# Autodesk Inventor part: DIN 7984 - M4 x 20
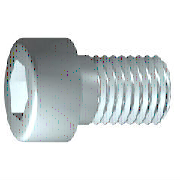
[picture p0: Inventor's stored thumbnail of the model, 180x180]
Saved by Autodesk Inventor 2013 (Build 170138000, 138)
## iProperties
Created: 2012-02
Part Number: DIN 7984 - M4 x 20
Material: Stahl, weich
Description: Zylinderkopfschraube
Document SubType Name: Modeling
Standard: DIN 7984
Designer: Ente
Standard Revision: 1985
Standards Organization: DIN
Language: de-DE
Size Designation: M4 x 20
Categories: <MemberInstance><Categories><Category DisplayName="Verbindungselemente" InternalName="e4da775c-781d-43d5-af7c-5136215cf5a6" Mnemonic="FSTN"><Category DisplayNam
Density: 1 g/cm^3
IsCustomPart: 0
Author: Ente
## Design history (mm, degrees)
sketch "Skizze1"
  geometry: L1 (0.333, 0)-(20, 0); L2 (20, 0)-(20, 2); L3 (20, 2)-(2.1, 2); L4 (2.1, 2)-(1.67, 2); L5 (1.67, 2)-(0, 2); L6 (0, 2)-(0, 3.5); L7 (0, 3.5)-(-2.8, 3.5); L8 (-2.8, 3.5)-(-2.8, 1.443); L9 (-2.8, 1.443)-(-0.5, 1.443); L10 (-0.5, 1.443)-(0.333, 0); L11 (-7.36, 0)-(24.56, 0) reference; L12 (0, -0.7)-(0, 4.2) reference; L13 (2.1, 2)-(0, 2)
  constraints: 22 end point, 6 parallel, 2 collinear, 2 perpendicular, 1 horizontal, 1 point on line
  dimensions: "d1" = 17.9 distance from line of L3.end L2 (= GEL); "d2" = 0.42952 distance of L4.end L3.end (computed from GAL); "d3" = 2.8 distance between parallel lines of L8 L6 (= KOH); "d4" = 2.3 distance of L8.end L9.end (= INTI); "d5" = 60 deg angle of L10 L1; "d6" = 4 diameter of L3 L1 (= GD); "d7" = 4 diameter of L5 L1 (= BDM); "d8" = 2.88675 diameter of L9 L1 (= 1.1547 x SW); "d9" = 7 diameter of L7 L1 (= KOD); "d26" = 20 distance between parallel lines of L12 L2 (= NLG)
revolve "Körper" sketch "Skizze1" stored, may be unused: angle "d10" = 90 deg
sketch "Skizze2"
  geometry: L1 (0, -4.9)-(0, 4.9) reference; L2 (-4.9, 0)-(4.9, 0) reference; L3 (1.443, 0)-(0.722, -1.25); L4 (0.722, -1.25)-(-0.722, -1.25); L5 (-0.722, -1.25)-(-1.443, 0); L6 (-1.443, 0)-(-0.722, 1.25); L7 (-0.722, 1.25)-(0.722, 1.25); L8 (0.722, 1.25)-(1.443, 0); 2 further points
  constraints: 12 end point, 1 coincident, 1 horizontal alignment, 1 point on line, 12 other
extrude "Loch" join sketch "Skizze2" stored distance "d11" = 10; taper "d12" = 0 deg
workplane "Work Plane1"
fillet "Fillet2" dims "d30" = 0.1 (= R)
body "Solid1"
fillet "Rundung1" dims "d17" = 0.4 (= RR)
feature "Gewinde" dims "d13" = 17.9 (= GEL), "d14" = 0
chamfer "Fase1" distance "d15" = 0.42941 (= -0.5 x SPD + 0.5 x GD); stored, may be unused: second distance "d16" = 0.42941 (= GUL), angle "d27" = 45 deg
other parameters: "GD" = 4 (= NND) [user parameter; used in 2 equation terms], "NLG" = 20 [user parameter; used in 1 equation term], "GEL" = 17.9 [user parameter; used in 2 equation terms], "KOD" = 7 [user parameter; used in 1 equation term], "KOH" = 2.8 [user parameter; used in 1 equation term], "INTI" = 2.3 [user parameter; used in 1 equation term], "GAL" = 0.42941 (= 0.61345 x PTC) [user parameter; used in 1 equation term], "GUL" = 0.42941 (= 0.61345 x PTC) [user parameter; used in 1 equation term], "BDM" = 4 (= NND) [user parameter; used in 1 equation term], "SW" = 2.5 [user parameter; used in 2 equation terms], "RR" = 0.4 [user parameter; used in 1 equation term], "SPD" = 3.14117 (= NND - 1.2269 x PTC) [user parameter; used in 1 equation term], "d19" = 0, "d28" = 0, "d29" = 0, "R" = 0.1 [user parameter; used in 1 equation term], "TOA" = 30 deg [user parameter], "GD1" = 3.14117 (= THREADDIA - 1.2269 x PTC) [user parameter], "THREADDIA" = 4 [user parameter; used in 1 equation term], "FAWI" = 45 deg [user parameter], "ANG" = 120 deg [user parameter], "TPU" = 14.28571 (computed from PTC) [user parameter], "PTC" = 0.7 [user parameter; used in 5 equation terms], "NND" = 4 [user parameter; used in 3 equation terms], "E0" = 2.8875 (= 1.155 x SW) [user parameter]
